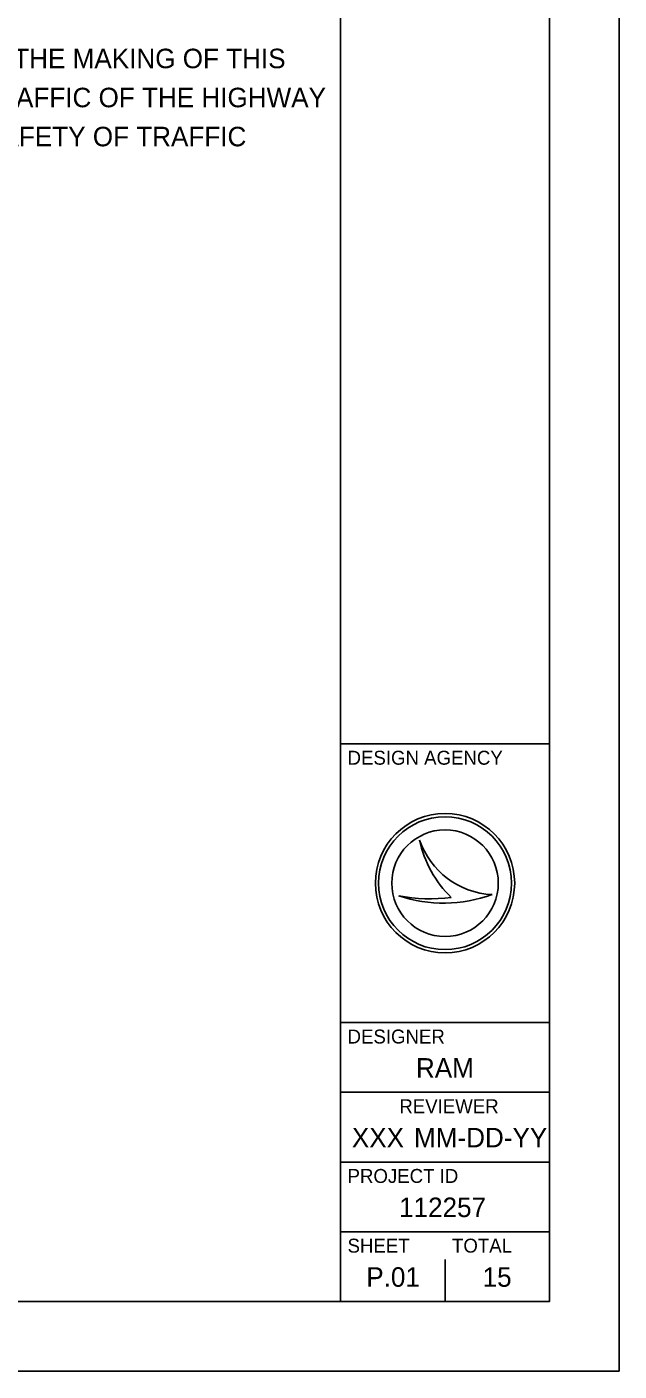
# Model space of a CAD drawing. Extents: x 0 to 34, y 0 to 22.
# Drawn here: x 29.75 to 34, y 0 to 9.64 of the extents above; entities that cross this region are included whole.
import ezdxf

# ---------------------------------------------------------------- set-up
doc = ezdxf.new("R2010")
doc.units = 0
for name, color, linetype in [('SH_Border', 7, 'Continuous'), ('SH_Cut_Line', 7, 'Continuous'), ('SH_Data', 7, 'Continuous'), ('SH_Text', 7, 'Continuous')]:
    doc.layers.add(name, color=color, linetype=linetype)

msp = doc.modelspace()

# ---------------------------------------------------------------- linework, layer by layer
at = {"layer": 'SH_Border'}
for p, q in [((32, 0.5), (32, 21.5)), ((32, 4.5), (33.5, 4.5)), ((32, 2.5), (33.5, 2.5)), ((32, 2), (33.5, 2)), ((32, 1.5), (33.5, 1.5)), ((32, 1), (33.5, 1))]:
    msp.add_line(p, q, dxfattribs=at)
msp.add_lwpolyline([(1.5, 21.5), (33.5, 21.5), (33.5, 0.5), (1.5, 0.5)], close=True, dxfattribs=at)
at = {"layer": 'SH_Cut_Line'}
msp.add_lwpolyline([(0, 0), (34, 0), (34, 22), (0, 22)], close=True, dxfattribs=at)
at = {"layer": 'SH_Data'}
for p, q in [((32.5674, 3.8096), (32.5675, 3.8096)), ((32.75, 3.5), (32.75, 3.5)), ((32.4172, 3.4095), (32.4172, 3.4095)), ((33.0873, 3.4185), (33.0873, 3.4185)), ((32.75, 0.5), (32.75, 0.8)), ((32.375, 0.675), (32.375, 0.675))]:
    msp.add_line(p, q, dxfattribs=at)
for radius in [0.5, 0.4768, 0.4768, 0.3822]:
    msp.add_circle((32.75, 3.5), radius, dxfattribs=at)
for centre, radius, start, end in [((33.1159, 3.9976), 0.5798, 198.92567, 198.93195), ((33.3467, 3.9701), 0.7956, 191.63793, 191.64215), ((33.1159, 3.9976), 0.5798, 198.93195, 267.16574), ((33.3467, 3.9701), 0.7956, 191.64215, 226.09467), ((32.7394, 4.37), 1.0131, 251.45764, 290.08324), ((32.648, 4.6543), 1.2661, 259.49639, 259.49952), ((32.7394, 4.37), 1.0131, 251.45274, 251.45764), ((32.648, 4.6543), 1.2661, 259.49952, 276.66723)]:
    msp.add_arc(centre, radius, start, end, dxfattribs=at)

# ---------------------------------------------------------------- texts
for s, height, p in [('DESIGN AGENCY', 0.1, (32.05, 4.35)), ('DESIGNER', 0.1, (32.05, 2.35)), ('RAM', 0.14, (32.5412, 2.105)), ('REVIEWER', 0.1, (32.4218, 1.85)), ('XXX', 0.14, (32.0809, 1.605)), ('MM-DD-YY', 0.14, (32.5273, 1.605)), ('PROJECT ID', 0.1, (32.05, 1.35)), ('112257', 0.14, (32.4198, 1.105)), ('SHEET', 0.1, (32.05, 0.85)), ('TOTAL', 0.1, (32.8, 0.85)), ('P.01', 0.14, (32.1844, 0.605)), ('15', 0.14, (33.0197, 0.605))]:
    msp.add_text(s, height=height, dxfattribs=at).set_placement(p)
at = {"layer": 'SH_Text'}
for s, p in [('I HEREBY APPROVE THESE PLANS AND DECLARE THAT THE MAKING OF THIS', (24.5, 9.346)), ('IMPROVEMENT WILL NOT REQUIRE THE CLOSING TO TRAFFIC OF THE HIGHWAY', (24.5, 9.066)), ('AND THAT PROVISIONS FOR THE MAINTENANCE AND SAFETY OF TRAFFIC ', (24.5, 8.786))]:
    msp.add_text(s, height=0.14, dxfattribs=at).set_placement(p)

doc.saveas('drawing.dxf')
